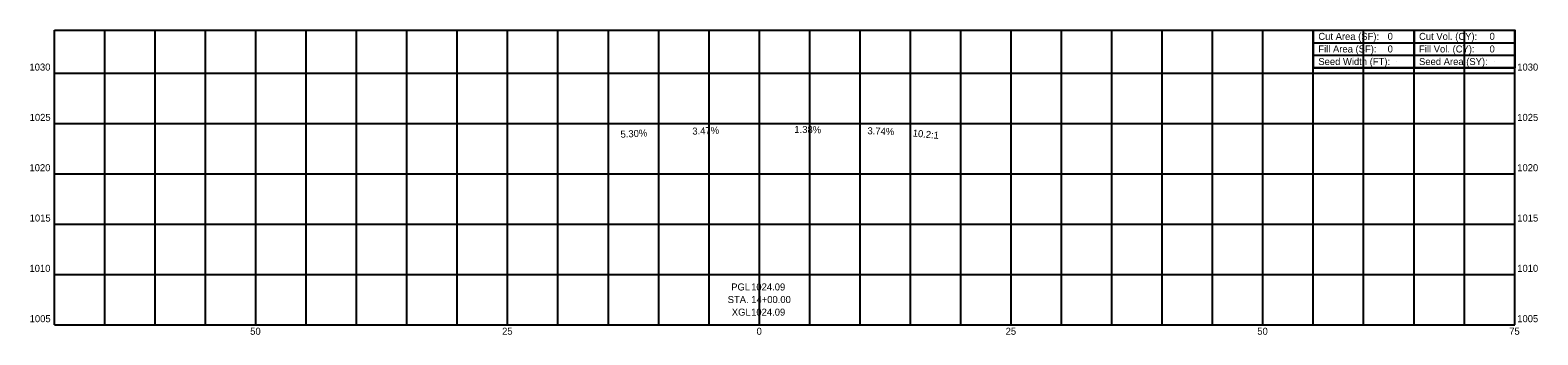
# Model space of a CAD drawing. Extents: x -72 to 77, y 1004 to 1034.
import ezdxf

# ---------------------------------------------------------------- set-up
doc = ezdxf.new("R2010")
doc.units = 0
for name, color, linetype in [('Default', 7, 'Continuous'), ('DT_X_Break_Line', 7, 'Continuous'), ('DT_X_Spot_Elev', 7, 'Continuous'), ('DT_X_Void', 7, 'Continuous'), ('SH_Data', 7, 'Continuous')]:
    doc.layers.add(name, color=color, linetype=linetype)

msp = doc.modelspace()

# ---------------------------------------------------------------- linework, layer by layer
at = {"layer": 'Default'}
msp.add_circle((75, 1034.27), 0.000417, dxfattribs=at)
msp.add_circle((75, 1034.27), 0.000417, dxfattribs=at)
msp.add_circle((75, 1034.27), 0.000417, dxfattribs=at)
msp.add_circle((75, 1034.27), 0.000417, dxfattribs=at)
msp.add_circle((75, 1034.27), 0.000417, dxfattribs=at)
msp.add_circle((75, 1034.27), 0.000417, dxfattribs=at)
msp.add_circle((75, 1034.27), 0.000417, dxfattribs=at)
msp.add_circle((75, 1034.27), 0.000417, dxfattribs=at)
msp.add_circle((75, 1034.27), 0.000417, dxfattribs=at)
msp.add_circle((75, 1034.27), 0.000417, dxfattribs=at)
msp.add_circle((75, 1034.27), 0.000417, dxfattribs=at)
msp.add_circle((75, 1034.27), 0.000417, dxfattribs=at)
at = {"layer": 'DT_X_Break_Line'}
for p, q in [((-70, 1034.27), (75, 1034.27)), ((-70, 1005), (-70, 1034.27)), ((-65, 1005), (-65, 1034.27)), ((-60, 1005), (-60, 1034.27)), ((-55, 1005), (-55, 1034.27)), ((-50, 1005), (-50, 1034.27)), ((-45, 1005), (-45, 1034.27)), ((-40, 1005), (-40, 1034.27)), ((-35, 1005), (-35, 1034.27)), ((-30, 1005), (-30, 1034.27)), ((-25, 1005), (-25, 1034.27)), ((-20, 1005), (-20, 1034.27)), ((-15, 1005), (-15, 1034.27)), ((-10, 1005), (-10, 1034.27)), ((-5, 1005), (-5, 1034.27)), ((0, 1005), (0, 1034.27)), ((5, 1005), (5, 1034.27)), ((10, 1005), (10, 1034.27)), ((15, 1005), (15, 1034.27)), ((20, 1005), (20, 1034.27)), ((25, 1005), (25, 1034.27)), ((30, 1005), (30, 1034.27)), ((35, 1005), (35, 1034.27)), ((40, 1005), (40, 1034.27)), ((45, 1005), (45, 1034.27)), ((50, 1005), (50, 1034.27)), ((55, 1005), (55, 1034.27)), ((60, 1005), (60, 1034.27)), ((65, 1005), (65, 1034.27)), ((70, 1005), (70, 1034.27)), ((75, 1005), (75, 1034.27)), ((-70, 1030), (75, 1030)), ((-70, 1025), (75, 1025)), ((-70, 1020), (75, 1020)), ((-70, 1015), (75, 1015)), ((-70, 1010), (75, 1010)), ((-70, 1005), (75, 1005))]:
    msp.add_line(p, q, dxfattribs=at)
at = {"layer": 'DT_X_Void'}
msp.add_lwpolyline([(55, 1034.27), (75, 1034.27), (75, 1030.52), (55, 1030.52)], close=True, dxfattribs=at)
at = {"layer": 'SH_Data'}
for p, q in [((55, 1034.27), (75, 1034.27)), ((55, 1034.27), (55, 1031.77)), ((55, 1033.02), (75, 1033.02)), ((65, 1034.27), (65, 1030.52)), ((75, 1034.27), (75, 1031.77)), ((55, 1031.77), (75, 1031.77)), ((63.3, 1031.15), (63.3, 1031.15)), ((72.95, 1031.15), (72.95, 1031.15))]:
    msp.add_line(p, q, dxfattribs=at)
msp.add_lwpolyline([(55, 1031.77), (55, 1030.52), (75, 1030.52), (75, 1031.77)], dxfattribs=at)

# ---------------------------------------------------------------- texts
at = {"layer": 'DT_X_Spot_Elev'}
for s, p in [('Cut Area (SF):', (55.5, 1033.3)), ('0', (62.38, 1033.3)), ('Cut Vol. (CY):', (65.5, 1033.3)), ('0', (72.5, 1033.3)), ('Seed Width (FT):', (55.5, 1030.8)), ('Fill Area (SF):', (55.5, 1032.05)), ('0', (62.38, 1032.05)), ('Seed Area (SY):', (65.5, 1030.8)), ('Fill Vol. (CY):', (65.5, 1032.05)), ('0', (72.5, 1032.05)), ('1030', (-72.48, 1030.25)), ('1030', (75.25, 1030.25)), ('1025', (-72.46, 1025.25)), ('1025', (75.25, 1025.25)), ('1020', (-72.48, 1020.25)), ('1020', (75.25, 1020.25)), ('1015', (-72.46, 1015.25)), ('1015', (75.25, 1015.25)), ('1010', (-72.48, 1010.25)), ('1010', (75.25, 1010.25)), ('PGL ', (-2.8, 1008.4)), ('1024.09', (-0.82, 1008.4)), ('STA. 14+00.00', (-3.15, 1007.15)), ('XGL ', (-2.74, 1005.9)), ('1024.09', (-0.82, 1005.9)), ('1005', (-72.46, 1005.25)), ('50', (-50.56, 1004)), ('25', (-25.55, 1004)), ('0', (-0.28, 1004)), ('25', (24.45, 1004)), ('50', (49.44, 1004)), ('75', (74.45, 1004)), ('1005', (75.25, 1005.25))]:
    msp.add_text(s, height=0.7, dxfattribs=at).set_placement(p)
for s, rotation, p in [('5.30%', 3.0325, (-13.77, 1023.57)), ('3.47%', 1.9869, (-6.65, 1023.88)), ('1.38%', 359.2066, (3.47, 1024.06)), ('3.74%', 357.8593, (10.72, 1023.93)), ('10.2:1', 354.4169, (15.2, 1023.71)), ('10.2:1', 354.4106, (15.2, 1023.71)), ('10.2:1', 354.4169, (15.2, 1023.71))]:
    msp.add_text(s, height=0.7, rotation=rotation, dxfattribs=at).set_placement(p)

doc.saveas('drawing.dxf')
